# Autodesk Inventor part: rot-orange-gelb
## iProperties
Created: 2004-10
Part Number: rot-orange-gelb
Document SubType Name: Modeling
Designer: sahrens
Manufacturer: Standard
Standards Organization: Custom
Author: sahrens
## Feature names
1. Extrusion1
2. Rundung2 [Fillet]
